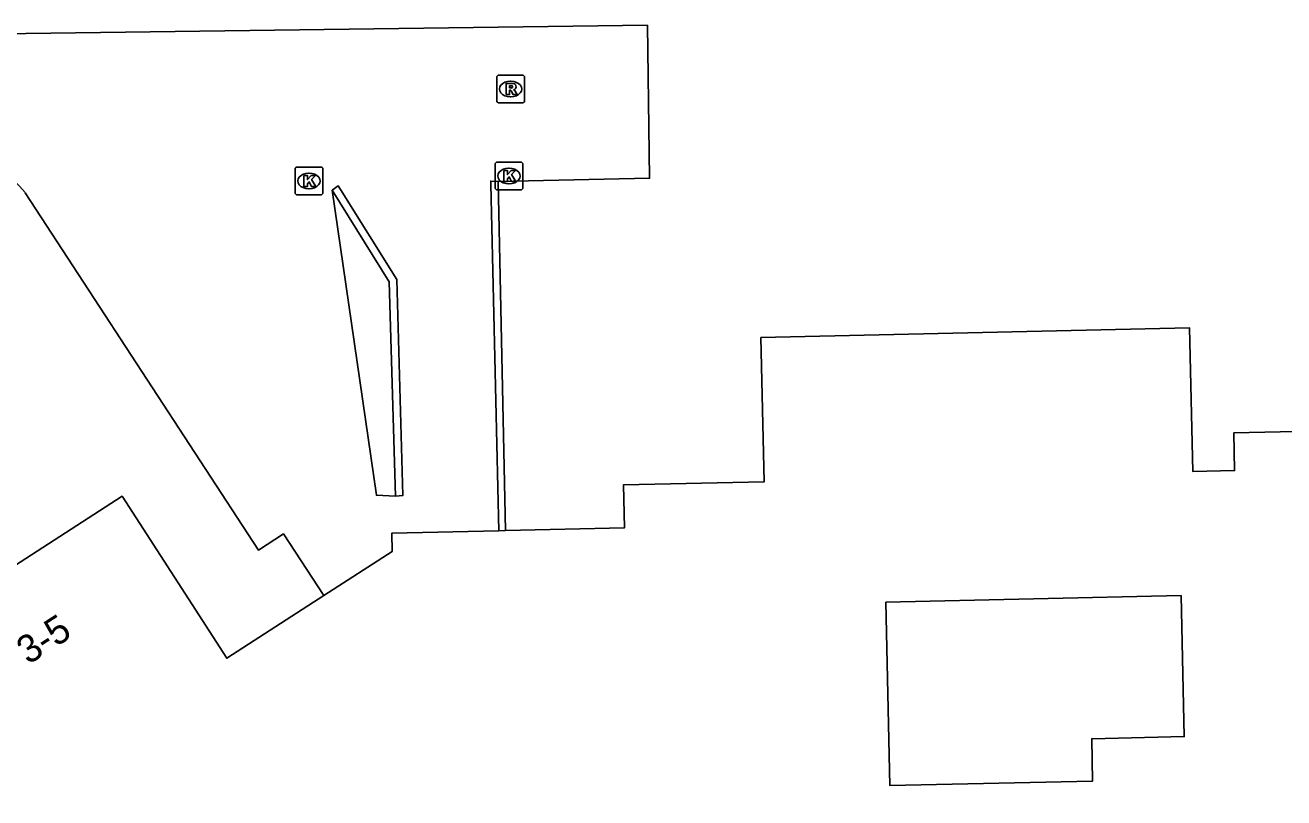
# Model space of a CAD drawing. Extents: x 162791 to 163827, y 385795 to 386523.
# Drawn here: x 163217.83 to 163263.14, y 386466.81 to 386494.62 of the extents above; entities that cross this region are included whole.
import ezdxf

# ---------------------------------------------------------------- set-up
doc = ezdxf.new("R2010")
doc.units = 0
for name, color, linetype in [('IMGEO_Kolk', 7, 'Continuous'), ('IMGEO_Muur', 7, 'Continuous'), ('IMGEO_Pand', 7, 'Continuous'), ('IMGEO_Pand_nummerreeks', 7, 'Continuous'), ('IMGEO_Rioolput', 7, 'Continuous'), ('IMGEO_Voetpad_open', 7, 'Continuous')]:
    doc.layers.add(name, color=color, linetype=linetype)

msp = doc.modelspace()

# ---------------------------------------------------------------- linework, layer by layer
at = {"layer": 'IMGEO_Kolk'}
for p, q in [((163234.821, 386489.693), (163235.673, 386489.693)), ((163227.545, 386488.588), (163227.545, 386489.44)), ((163227.62, 386489.514), (163228.472, 386489.514)), ((163228.033, 386489.294), (163228.058, 386489.294)), ((163228.546, 386489.44), (163228.546, 386488.588)), ((163234.746, 386488.767), (163234.746, 386489.619)), ((163235.234, 386489.473), (163235.259, 386489.473)), ((163235.747, 386489.619), (163235.747, 386488.767)), ((163235.257, 386488.913), (163235.232, 386488.913)), ((163228.472, 386488.514), (163227.62, 386488.514)), ((163228.056, 386488.734), (163228.031, 386488.734)), ((163235.673, 386488.693), (163234.821, 386488.693))]:
    msp.add_line(p, q, dxfattribs=at)
for points in [[(163234.821, 386489.693), (163235.673, 386489.693)], [(163227.545, 386488.588), (163227.545, 386489.44)], [(163227.62, 386489.514), (163228.472, 386489.514)], [(163227.866, 386489.214), (163227.989, 386489.214), (163227.989, 386489.063), (163228.119, 386489.214), (163228.283, 386489.214), (163228.137, 386489.063), (163228.29, 386488.814), (163228.138, 386488.814), (163228.053, 386488.978), (163227.989, 386488.911), (163227.989, 386488.814), (163227.866, 386488.814), (163227.866, 386489.214)], [(163228.546, 386489.44), (163228.546, 386488.588)], [(163234.746, 386488.767), (163234.746, 386489.619)], [(163235.067, 386489.393), (163235.19, 386489.393), (163235.19, 386489.242), (163235.32, 386489.393), (163235.484, 386489.393), (163235.338, 386489.242), (163235.491, 386488.993), (163235.339, 386488.993), (163235.254, 386489.157), (163235.19, 386489.09), (163235.19, 386488.993), (163235.067, 386488.993), (163235.067, 386489.393)], [(163235.747, 386489.619), (163235.747, 386488.767)], [(163228.472, 386488.514), (163227.62, 386488.514)], [(163235.673, 386488.693), (163234.821, 386488.693)]]:
    msp.add_lwpolyline(points, dxfattribs=at)
for centre, start, end in [((163234.823, 386489.617), 91.552, 178.448), ((163234.823, 386489.617), 91.552, 178.448), ((163235.671, 386489.617), 1.552, 88.448), ((163235.671, 386489.617), 1.552, 88.448), ((163227.622, 386489.438), 91.552, 178.448), ((163227.622, 386489.438), 91.552, 178.448), ((163228.47, 386489.438), 1.552, 88.448), ((163228.47, 386489.438), 1.552, 88.448), ((163234.823, 386488.769), 181.552, 268.448), ((163234.823, 386488.769), 181.552, 268.448), ((163235.671, 386488.769), 271.552, 358.448), ((163235.671, 386488.769), 271.552, 358.448), ((163227.622, 386488.59), 181.552, 268.448), ((163227.622, 386488.59), 181.552, 268.448), ((163228.47, 386488.59), 271.552, 358.448), ((163228.47, 386488.59), 271.552, 358.448)]:
    msp.add_arc(centre, 0.0765, start, end, dxfattribs=at)
for centre, major_axis, ratio, start_param, end_param in [((163228.032, 386489.014), (-0.387, 0.002), 0.722429, 4.712389, 7.853982), ((163228.057, 386489.014), (-0.39, 0.002), 0.717154, 1.570796, 4.712389), ((163235.233, 386489.193), (-0.387, 0.002), 0.722429, 4.712389, 7.853982), ((163235.258, 386489.193), (-0.39, 0.002), 0.717154, 1.570796, 4.712389)]:
    msp.add_ellipse(centre, major_axis=major_axis, ratio=ratio, start_param=start_param, end_param=end_param, dxfattribs=at)
at = {"layer": 'IMGEO_Muur'}
for points in [[(163228.876, 386488.684), (163229.102, 386488.834), (163229.186, 386488.701), (163231.215, 386485.47), (163231.426, 386477.696), (163231.156, 386477.673)], [(163234.878, 386476.422), (163234.595, 386488.899), (163234.593, 386489.009), (163234.862, 386488.99)], [(163234.862, 386488.99), (163235.127, 386476.428)], [(163231.156, 386477.673), (163230.932, 386485.385), (163228.876, 386488.684)]]:
    msp.add_lwpolyline(points, dxfattribs=at)
at = {"layer": 'IMGEO_Pand'}
for points in [[(163235.127, 386476.428), (163239.403, 386476.524), (163239.368, 386478.072), (163244.437, 386478.187), (163244.32, 386483.376), (163259.751, 386483.725), (163259.868, 386478.556), (163261.371, 386478.59), (163261.34, 386479.944), (163269.146, 386480.121)], [(163211.892, 386465.954), (163215.708, 386468.416), (163213.144, 386472.391), (163221.319, 386477.666), (163225.084, 386471.832), (163228.579, 386474.087)], [(163228.579, 386474.087), (163231.038, 386475.673), (163231.024, 386476.335), (163234.878, 386476.422)], [(163235.127, 386476.428), (163234.878, 386476.422)], [(163248.815, 386473.848), (163259.444, 386474.088), (163259.558, 386469.012), (163256.227, 386468.936), (163256.261, 386467.414), (163248.964, 386467.249), (163248.815, 386473.848)]]:
    msp.add_lwpolyline(points, dxfattribs=at)
at = {"layer": 'IMGEO_Rioolput'}
for p, q in [((163234.806, 386491.896), (163234.806, 386492.748)), ((163234.881, 386492.822), (163235.733, 386492.822)), ((163235.294, 386492.602), (163235.319, 386492.602)), ((163235.807, 386492.748), (163235.807, 386491.896)), ((163235.317, 386492.042), (163235.292, 386492.042)), ((163235.733, 386491.822), (163234.881, 386491.822))]:
    msp.add_line(p, q, dxfattribs=at)
for points in [[(163234.806, 386491.896), (163234.806, 386492.748)], [(163234.881, 386492.822), (163235.733, 386492.822)], [(163235.395, 386492.52), (163235.143, 386492.522), (163235.143, 386492.122)], [(163235.321, 386492.441), (163235.267, 386492.441), (163235.267, 386492.36)], [(163235.807, 386492.748), (163235.807, 386491.896)], [(163235.143, 386492.122), (163235.267, 386492.122), (163235.267, 386492.284), (163235.278, 386492.284)], [(163235.267, 386492.36), (163235.319, 386492.36)], [(163235.325, 386492.255), (163235.396, 386492.122), (163235.536, 386492.122), (163235.471, 386492.248)], [(163235.733, 386491.822), (163234.881, 386491.822)]]:
    msp.add_lwpolyline(points, dxfattribs=at)
for centre, radius, start, end in [((163234.883, 386492.746), 0.0765, 91.552, 178.448), ((163234.883, 386492.746), 0.0765, 91.552, 178.448), ((163235.327, 386492.345), 0.0964, 77.0061, 93.1865), ((163235.341, 386492.402), 0.0378, 276.6634, 79.6772), ((163235.394, 386492.41), 0.109, 350.3612, 89.416), ((163235.392, 386492.41), 0.112, 277.5842, 350.9817), ((163235.731, 386492.746), 0.0765, 1.552, 88.448), ((163235.731, 386492.746), 0.0765, 1.552, 88.448), ((163235.277, 386492.231), 0.0533, 26.0293, 88.6989), ((163235.303, 386492.549), 0.19, 274.7715, 282.9687), ((163235.376, 386492.195), 0.108, 29.5134, 73.7905), ((163234.883, 386491.898), 0.0765, 181.552, 268.448), ((163234.883, 386491.898), 0.0765, 181.552, 268.448), ((163235.731, 386491.898), 0.0765, 271.552, 358.448), ((163235.731, 386491.898), 0.0765, 271.552, 358.448)]:
    msp.add_arc(centre, radius, start, end, dxfattribs=at)
for centre, major_axis, ratio, start_param, end_param in [((163235.293, 386492.322), (-0.387, 0.002), 0.722429, 4.712389, 7.853982), ((163235.318, 386492.322), (-0.39, 0.002), 0.717154, 1.570796, 4.712389)]:
    msp.add_ellipse(centre, major_axis=major_axis, ratio=ratio, start_param=start_param, end_param=end_param, dxfattribs=at)
at = {"layer": 'IMGEO_Voetpad_open'}
for points in [[(163216.052, 386494.295), (163240.232, 386494.621), (163240.311, 386489.109), (163234.862, 386488.99)], [(163228.579, 386474.087), (163227.128, 386476.307), (163226.228, 386475.729), (163217.828, 386488.592)], [(163231.156, 386477.673), (163230.474, 386477.698), (163228.876, 386488.684)]]:
    msp.add_lwpolyline(points, dxfattribs=at)
msp.add_arc((163213.66, 386485.179), 5.387, 39.3166, 142.7964, dxfattribs=at)

# ---------------------------------------------------------------- texts
at = {"layer": 'IMGEO_Pand_nummerreeks'}
msp.add_text('3-5', height=1, rotation=32.8305, dxfattribs=at).set_placement((163217.942, 386471.583))

doc.saveas('drawing.dxf')
